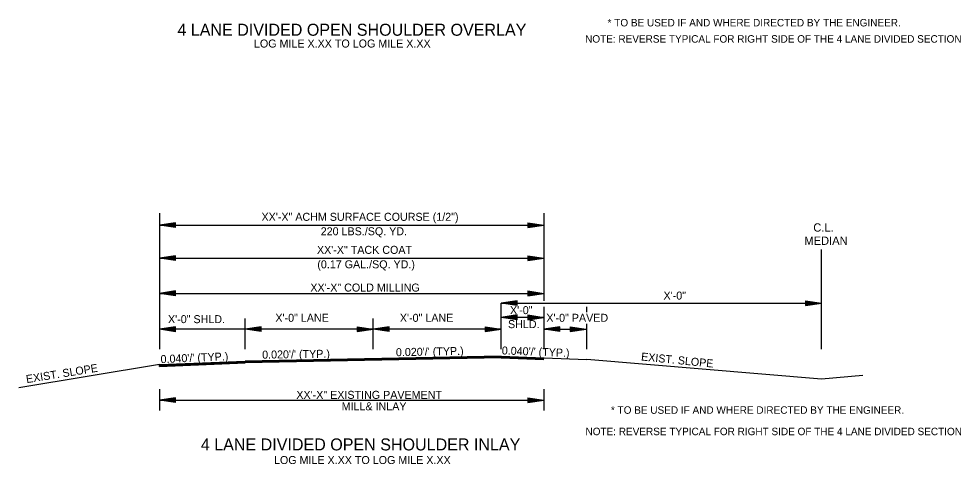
# Model space of a CAD drawing. Extents: x 542112 to 1930787, y -1968972 to 596640.
# Drawn here: x 546552 to 547435, y -1965039 to -1964622 of the extents above; entities that cross this region are included whole.
import ezdxf

# ---------------------------------------------------------------- set-up
doc = ezdxf.new("R2010")
doc.units = 0
doc.layers.add('R_Border Prem', color=7, linetype='Continuous')
doc.layers.add('R_Draft', color=7, linetype='Continuous')

msp = doc.modelspace()

# ---------------------------------------------------------------- linework, layer by layer
at = {"layer": 'R_Draft'}
for p, q in [((546683.85, -1964804.05), (546683.85, -1964931.48)), ((546698.85, -1964813.06), (546683.85, -1964815.31)), ((546683.85, -1964815.31), (547044.01, -1964815.31)), ((546698.85, -1964817.56), (546683.85, -1964815.31)), ((546698.85, -1964813.44), (546686.35, -1964815.31)), ((546698.85, -1964817.19), (546686.35, -1964815.31)), ((546698.85, -1964813.82), (546688.93, -1964815.31)), ((546698.85, -1964816.81), (546688.93, -1964815.31)), ((546698.85, -1964814.2), (546691.43, -1964815.31)), ((546698.85, -1964816.43), (546691.43, -1964815.31)), ((546698.85, -1964814.58), (546693.97, -1964815.31)), ((546698.85, -1964816.04), (546693.97, -1964815.31)), ((546698.85, -1964814.96), (546696.48, -1964815.31)), ((546698.85, -1964815.67), (546696.48, -1964815.31)), ((546698.85, -1964817.56), (546698.85, -1964813.06)), ((547029.01, -1964813.06), (547044.01, -1964815.31)), ((547029.01, -1964813.06), (547029.01, -1964817.56)), ((547029.01, -1964813.44), (547041.51, -1964815.31)), ((547029.01, -1964813.82), (547038.93, -1964815.31)), ((547029.01, -1964814.2), (547036.43, -1964815.31)), ((547029.01, -1964814.59), (547033.89, -1964815.31)), ((547029.01, -1964814.96), (547031.38, -1964815.31)), ((547029.01, -1964817.56), (547044.01, -1964815.31)), ((547029.01, -1964816.05), (547033.89, -1964815.31)), ((547029.01, -1964816.81), (547038.93, -1964815.31)), ((547029.01, -1964817.19), (547041.51, -1964815.31)), ((547029.01, -1964816.43), (547036.43, -1964815.31)), ((547029.01, -1964815.67), (547031.38, -1964815.31)), ((547304.03, -1964931.31), (547304.03, -1964837.92)), ((546698.85, -1964843.93), (546683.85, -1964846.18)), ((546683.85, -1964846.18), (547044.01, -1964846.18)), ((546698.85, -1964848.43), (546683.85, -1964846.18)), ((546698.85, -1964844.31), (546686.35, -1964846.18)), ((546698.85, -1964848.06), (546686.35, -1964846.18)), ((546698.85, -1964844.69), (546688.93, -1964846.18)), ((546698.85, -1964847.68), (546688.93, -1964846.18)), ((546698.85, -1964845.07), (546691.43, -1964846.18)), ((546698.85, -1964847.3), (546691.43, -1964846.18)), ((546698.85, -1964845.45), (546693.97, -1964846.18)), ((546698.85, -1964846.91), (546693.97, -1964846.18)), ((546698.85, -1964845.83), (546696.48, -1964846.18)), ((546698.85, -1964846.54), (546696.48, -1964846.18)), ((546698.85, -1964848.43), (546698.85, -1964843.93)), ((547029.01, -1964843.93), (547044.01, -1964846.18)), ((547029.01, -1964843.93), (547029.01, -1964848.43)), ((547029.01, -1964844.31), (547041.51, -1964846.18)), ((547029.01, -1964844.69), (547038.93, -1964846.18)), ((547029.01, -1964845.07), (547036.43, -1964846.18)), ((547029.01, -1964845.46), (547033.89, -1964846.18)), ((547029.01, -1964845.83), (547031.38, -1964846.18)), ((547029.01, -1964848.43), (547044.01, -1964846.18)), ((547029.01, -1964846.92), (547033.89, -1964846.18)), ((547029.01, -1964847.68), (547038.93, -1964846.18)), ((547029.01, -1964848.06), (547041.51, -1964846.18)), ((547029.01, -1964847.3), (547036.43, -1964846.18)), ((547029.01, -1964846.54), (547031.38, -1964846.18)), ((546698.85, -1964876.86), (546683.85, -1964879.11)), ((546698.85, -1964877.24), (546686.35, -1964879.11)), ((546698.85, -1964877.62), (546688.93, -1964879.11)), ((546698.85, -1964877.99), (546691.43, -1964879.11)), ((546698.85, -1964878.38), (546693.97, -1964879.11)), ((546698.85, -1964878.76), (546696.48, -1964879.11)), ((546698.85, -1964881.36), (546698.85, -1964876.86)), ((547029.01, -1964876.86), (547044.01, -1964879.11)), ((547029.01, -1964876.86), (547029.01, -1964881.36)), ((547029.01, -1964877.24), (547041.51, -1964879.11)), ((547029.01, -1964877.62), (547038.93, -1964879.11)), ((547029.01, -1964877.99), (547036.43, -1964879.11)), ((547029.01, -1964878.38), (547033.89, -1964879.11)), ((547029.01, -1964878.76), (547031.38, -1964879.11)), ((546683.85, -1964879.11), (547044.01, -1964879.11)), ((546698.85, -1964881.36), (546683.85, -1964879.11)), ((546698.85, -1964880.99), (546686.35, -1964879.11)), ((546698.85, -1964880.6), (546688.93, -1964879.11)), ((546698.85, -1964880.23), (546691.43, -1964879.11)), ((546698.85, -1964879.84), (546693.97, -1964879.11)), ((546698.85, -1964879.46), (546696.48, -1964879.11)), ((547019.03, -1964886.13), (547004.03, -1964888.38)), ((547019.03, -1964886.5), (547006.54, -1964888.38)), ((547019.03, -1964886.88), (547009.12, -1964888.38)), ((547019.03, -1964887.26), (547011.62, -1964888.38)), ((547019.03, -1964890.63), (547019.03, -1964886.13)), ((547029.01, -1964881.36), (547044.01, -1964879.11)), ((547029.01, -1964879.85), (547033.89, -1964879.11)), ((547029.01, -1964880.6), (547038.93, -1964879.11)), ((547029.01, -1964880.99), (547041.51, -1964879.11)), ((547029.01, -1964880.23), (547036.43, -1964879.11)), ((547029.01, -1964879.46), (547031.38, -1964879.11)), ((547289.03, -1964886.13), (547304.03, -1964888.38)), ((547289.03, -1964886.13), (547289.03, -1964890.63)), ((547289.03, -1964886.5), (547301.53, -1964888.38)), ((547289.03, -1964886.88), (547298.95, -1964888.38)), ((547289.03, -1964887.26), (547296.45, -1964888.38)), ((547004.03, -1964931.31), (547004.03, -1964888.38)), ((547004.03, -1964888.38), (547304.03, -1964888.38)), ((547019.03, -1964890.63), (547004.03, -1964888.38)), ((547019.03, -1964890.25), (547006.54, -1964888.38)), ((547019.03, -1964889.87), (547009.12, -1964888.38)), ((547019.03, -1964889.49), (547011.62, -1964888.38)), ((547019.03, -1964887.64), (547014.16, -1964888.38)), ((547019.03, -1964889.1), (547014.16, -1964888.38)), ((547019.03, -1964888.02), (547016.66, -1964888.38)), ((547019.03, -1964888.73), (547016.66, -1964888.38)), ((547084.29, -1964896.77), (547084.29, -1964891.87)), ((547289.03, -1964887.65), (547293.91, -1964888.38)), ((547289.03, -1964888.02), (547291.4, -1964888.38)), ((547289.03, -1964890.63), (547304.03, -1964888.38)), ((547289.03, -1964889.11), (547293.91, -1964888.38)), ((547289.03, -1964889.87), (547298.95, -1964888.38)), ((547289.03, -1964890.25), (547301.53, -1964888.38)), ((547289.03, -1964889.49), (547296.45, -1964888.38)), ((547289.03, -1964888.73), (547291.4, -1964888.38)), ((546764.11, -1964931.31), (546764.11, -1964902.76)), ((546764.11, -1964931.48), (546764.11, -1964902.76)), ((546884.11, -1964931.31), (546884.11, -1964902.76)), ((547019.03, -1964899.36), (547004.03, -1964901.61)), ((547044.01, -1964901.61), (547004.03, -1964901.61)), ((547019.03, -1964903.86), (547004.03, -1964901.61)), ((547004.03, -1964912.65), (547004.03, -1964902.76)), ((547019.03, -1964899.74), (547006.54, -1964901.61)), ((547019.03, -1964903.49), (547006.54, -1964901.61)), ((547019.03, -1964900.12), (547009.12, -1964901.61)), ((547019.03, -1964903.11), (547009.12, -1964901.61)), ((547019.03, -1964900.5), (547011.62, -1964901.61)), ((547019.03, -1964902.73), (547011.62, -1964901.61)), ((547019.03, -1964900.88), (547014.16, -1964901.61)), ((547019.03, -1964902.34), (547014.16, -1964901.61)), ((547019.03, -1964901.26), (547016.66, -1964901.61)), ((547019.03, -1964901.97), (547016.66, -1964901.61)), ((547019.03, -1964903.86), (547019.03, -1964899.36)), ((547029.01, -1964899.36), (547044.01, -1964901.61)), ((547029.01, -1964899.36), (547029.01, -1964903.86)), ((547029.01, -1964899.74), (547041.51, -1964901.61)), ((547029.01, -1964900.12), (547038.93, -1964901.61)), ((547029.01, -1964900.5), (547036.43, -1964901.61)), ((547029.01, -1964900.89), (547033.89, -1964901.61)), ((547029.01, -1964901.26), (547031.38, -1964901.61)), ((547029.01, -1964903.86), (547044.01, -1964901.61)), ((547029.01, -1964902.35), (547033.89, -1964901.61)), ((547029.01, -1964903.11), (547038.93, -1964901.61)), ((547029.01, -1964903.49), (547041.51, -1964901.61)), ((547029.01, -1964902.73), (547036.43, -1964901.61)), ((547029.01, -1964901.97), (547031.38, -1964901.61)), ((546698.85, -1964910.57), (546683.85, -1964912.82)), ((546764.11, -1964912.82), (546683.85, -1964912.82)), ((546698.85, -1964915.07), (546683.85, -1964912.82)), ((546698.85, -1964910.94), (546686.35, -1964912.82)), ((546698.85, -1964914.69), (546686.35, -1964912.82)), ((546698.85, -1964911.33), (546688.93, -1964912.82)), ((546698.85, -1964914.31), (546688.93, -1964912.82)), ((546698.85, -1964911.7), (546691.43, -1964912.82)), ((546698.85, -1964913.94), (546691.43, -1964912.82)), ((546698.85, -1964912.08), (546693.97, -1964912.82)), ((546698.85, -1964913.55), (546693.97, -1964912.82)), ((546698.85, -1964912.47), (546696.48, -1964912.82)), ((546698.85, -1964913.17), (546696.48, -1964912.82)), ((546698.85, -1964915.07), (546698.85, -1964910.57)), ((546779.11, -1964910.4), (546764.11, -1964912.65)), ((546884.11, -1964912.65), (546764.11, -1964912.65)), ((546779.11, -1964914.9), (546764.11, -1964912.65)), ((546779.11, -1964910.77), (546766.61, -1964912.65)), ((546779.11, -1964914.52), (546766.61, -1964912.65)), ((546779.11, -1964911.16), (546769.19, -1964912.65)), ((546779.11, -1964914.14), (546769.19, -1964912.65)), ((546779.11, -1964911.53), (546771.69, -1964912.65)), ((546779.11, -1964913.77), (546771.69, -1964912.65)), ((546779.11, -1964911.91), (546774.23, -1964912.65)), ((546779.11, -1964913.38), (546774.23, -1964912.65)), ((546779.11, -1964912.3), (546776.74, -1964912.65)), ((546779.11, -1964913), (546776.74, -1964912.65)), ((546779.11, -1964914.9), (546779.11, -1964910.4)), ((546869.11, -1964910.4), (546884.11, -1964912.65)), ((546869.11, -1964910.4), (546869.11, -1964914.9)), ((546869.11, -1964910.77), (546881.6, -1964912.65)), ((546869.11, -1964911.16), (546879.02, -1964912.65)), ((546869.11, -1964911.53), (546876.52, -1964912.65)), ((546869.11, -1964911.92), (546873.98, -1964912.65)), ((546869.11, -1964912.3), (546871.48, -1964912.65)), ((546869.11, -1964914.9), (546884.11, -1964912.65)), ((546869.11, -1964913.38), (546873.98, -1964912.65)), ((546869.11, -1964914.14), (546879.02, -1964912.65)), ((546869.11, -1964914.52), (546881.6, -1964912.65)), ((546869.11, -1964913.77), (546876.52, -1964912.65)), ((546869.11, -1964913), (546871.48, -1964912.65)), ((546899.11, -1964910.4), (546884.11, -1964912.65)), ((547004.03, -1964912.65), (546884.11, -1964912.65)), ((546899.11, -1964914.9), (546884.11, -1964912.65)), ((546899.11, -1964910.77), (546886.61, -1964912.65)), ((546899.11, -1964914.52), (546886.61, -1964912.65)), ((546899.11, -1964911.16), (546889.19, -1964912.65)), ((546899.11, -1964914.14), (546889.19, -1964912.65)), ((546899.11, -1964911.53), (546891.69, -1964912.65)), ((546899.11, -1964913.77), (546891.69, -1964912.65)), ((546899.11, -1964911.91), (546894.23, -1964912.65)), ((546899.11, -1964913.38), (546894.23, -1964912.65)), ((546899.11, -1964912.3), (546896.74, -1964912.65)), ((546899.11, -1964913), (546896.74, -1964912.65)), ((546899.11, -1964914.9), (546899.11, -1964910.4)), ((546989.03, -1964910.4), (547004.03, -1964912.65)), ((546989.03, -1964910.4), (546989.03, -1964914.9)), ((546989.03, -1964910.77), (547001.53, -1964912.65)), ((546989.03, -1964911.16), (546998.95, -1964912.65)), ((546989.03, -1964911.53), (546996.45, -1964912.65)), ((546989.03, -1964911.92), (546993.91, -1964912.65)), ((546989.03, -1964912.3), (546991.4, -1964912.65)), ((546989.03, -1964914.9), (547004.03, -1964912.65)), ((546989.03, -1964913.38), (546993.91, -1964912.65)), ((546989.03, -1964914.14), (546998.95, -1964912.65)), ((546989.03, -1964914.52), (547001.53, -1964912.65)), ((546989.03, -1964913.77), (546996.45, -1964912.65)), ((546989.03, -1964913), (546991.4, -1964912.65)), ((547004.03, -1964931.31), (547004.03, -1964912.65)), ((547059.01, -1964910.4), (547044.01, -1964912.65)), ((547059.01, -1964914.9), (547044.01, -1964912.65)), ((547044.01, -1964912.65), (547083.56, -1964912.65)), ((547059.01, -1964910.77), (547046.52, -1964912.65)), ((547059.01, -1964914.52), (547046.52, -1964912.65)), ((547059.01, -1964911.16), (547049.1, -1964912.65)), ((547059.01, -1964914.14), (547049.1, -1964912.65)), ((547059.01, -1964911.53), (547051.59, -1964912.65)), ((547059.01, -1964913.77), (547051.59, -1964912.65)), ((547059.01, -1964911.91), (547054.14, -1964912.65)), ((547059.01, -1964913.38), (547054.14, -1964912.65)), ((547059.01, -1964912.3), (547056.64, -1964912.65)), ((547059.01, -1964913), (547056.64, -1964912.65)), ((547059.01, -1964914.9), (547059.01, -1964910.4)), ((547068.56, -1964910.4), (547083.56, -1964912.65)), ((547068.56, -1964910.4), (547068.56, -1964914.9)), ((547068.56, -1964910.77), (547081.05, -1964912.65)), ((547068.56, -1964911.16), (547078.47, -1964912.65)), ((547068.56, -1964911.53), (547075.97, -1964912.65)), ((547068.56, -1964911.92), (547073.43, -1964912.65)), ((547068.56, -1964912.3), (547070.93, -1964912.65)), ((547068.56, -1964914.9), (547083.56, -1964912.65)), ((547068.56, -1964913.38), (547073.43, -1964912.65)), ((547068.56, -1964914.14), (547078.47, -1964912.65)), ((547068.56, -1964914.52), (547081.05, -1964912.65)), ((547068.56, -1964913.77), (547075.97, -1964912.65)), ((547068.56, -1964913), (547070.93, -1964912.65)), ((547084.29, -1964931.31), (547084.29, -1964907.62)), ((547004.03, -1964937.86), (546764.11, -1964942.65)), ((547004.03, -1964938.16), (546764.11, -1964942.95)), ((547004.03, -1964938.46), (546764.12, -1964943.25)), ((547004.03, -1964938.76), (546764.12, -1964943.55)), ((547004.03, -1964939.06), (546764.13, -1964943.85)), ((547004.03, -1964939.36), (546764.14, -1964944.15)), ((547004.03, -1964939.56), (546764.14, -1964944.35)), ((547003.97, -1964939.36), (547044.01, -1964940.96)), ((547003.97, -1964939.56), (547044.01, -1964941.16)), ((547003.99, -1964939.06), (547044.01, -1964940.66)), ((547004, -1964938.76), (547044.01, -1964940.36)), ((547004.01, -1964938.46), (547044.01, -1964940.06)), ((547004.02, -1964938.16), (547044.01, -1964939.76)), ((547004.03, -1964937.86), (547044.31, -1964939.47)), ((547044.01, -1964939.46), (547084.29, -1964941.07)), ((546683.85, -1964945.87), (546552.17, -1964967.81)), ((546683.85, -1964945.87), (546764.11, -1964942.65)), ((546683.85, -1964946.17), (546764.12, -1964942.95)), ((546683.85, -1964946.47), (546764.13, -1964943.25)), ((546683.85, -1964946.77), (546764.14, -1964943.55)), ((546683.85, -1964947.07), (546764.15, -1964943.85)), ((546683.85, -1964947.37), (546764.17, -1964944.15)), ((546683.85, -1964947.57), (546764.17, -1964944.35)), ((546683.85, -1964947.57), (546683.85, -1964945.87)), ((546683.85, -1964947.57), (546683.85, -1964945.87)), ((547303.96, -1964959.48), (547084.29, -1964941.07)), ((547342.79, -1964956.22), (547303.96, -1964959.48)), ((546683.85, -1964969.05), (546683.85, -1964989.05)), ((547044.01, -1964969.05), (547044.01, -1964989.05)), ((546698.85, -1964977.05), (546683.85, -1964979.3)), ((546683.85, -1964979.3), (547044.01, -1964979.3)), ((546698.85, -1964981.55), (546683.85, -1964979.3)), ((546698.85, -1964977.43), (546686.35, -1964979.3)), ((546698.85, -1964981.18), (546686.35, -1964979.3)), ((546698.85, -1964977.81), (546688.93, -1964979.3)), ((546698.85, -1964980.8), (546688.93, -1964979.3)), ((546698.85, -1964978.19), (546691.43, -1964979.3)), ((546698.85, -1964980.42), (546691.43, -1964979.3)), ((546698.85, -1964978.57), (546693.97, -1964979.3)), ((546698.85, -1964980.03), (546693.97, -1964979.3)), ((546698.85, -1964978.95), (546696.48, -1964979.3)), ((546698.85, -1964979.66), (546696.48, -1964979.3)), ((546698.85, -1964981.55), (546698.85, -1964977.05)), ((547029.01, -1964977.05), (547044.01, -1964979.3)), ((547029.01, -1964977.05), (547029.01, -1964981.55)), ((547029.01, -1964977.43), (547041.51, -1964979.3)), ((547029.01, -1964977.81), (547038.93, -1964979.3)), ((547029.01, -1964978.19), (547036.43, -1964979.3)), ((547029.01, -1964978.58), (547033.89, -1964979.3)), ((547029.01, -1964978.95), (547031.38, -1964979.3)), ((547029.01, -1964981.55), (547044.01, -1964979.3)), ((547029.01, -1964980.04), (547033.89, -1964979.3)), ((547029.01, -1964980.8), (547038.93, -1964979.3)), ((547029.01, -1964981.18), (547041.51, -1964979.3)), ((547029.01, -1964980.42), (547036.43, -1964979.3)), ((547029.01, -1964979.66), (547031.38, -1964979.3))]:
    msp.add_line(p, q, dxfattribs=at)
for points in [[(547044.01, -1964804.05), (547044.01, -1964886.15)], [(547044.01, -1964891.87), (547044.01, -1964931.31)]]:
    msp.add_lwpolyline(points, dxfattribs=at)

# ---------------------------------------------------------------- texts
at = {"layer": 'R_Border Prem'}
for s, p in [('* TO BE USED IF AND WHERE DIRECTED BY THE ENGINEER.', (547103.62, -1964628.97)), ('NOTE: REVERSE TYPICAL FOR RIGHT SIDE OF THE 4 LANE DIVIDED SECTION', (547082.56, -1964644.18)), ('* TO BE USED IF AND WHERE DIRECTED BY THE ENGINEER.', (547106.74, -1964991.97)), ('NOTE: REVERSE TYPICAL FOR RIGHT SIDE OF THE 4 LANE DIVIDED SECTION', (547082.92, -1965012.04))]:
    msp.add_text(s, height=7, dxfattribs=at).set_placement(p)
at = {"layer": 'R_Draft'}
for s, height, p in [('4 LANE DIVIDED OPEN SHOULDER OVERLAY', 11.25, (546700.7, -1964637.72)), ('LOG MILE X.XX TO LOG MILE X.XX', 7.5, (546772.38, -1964648.76)), ('XX\'-X" ACHM SURFACE COURSE (1/2")', 7.5, (546779.45, -1964811.15)), ('220 LBS./SQ. YD. ', 7.5, (546834.93, -1964824.69)), ('C.L.', 7.8, (547296.34, -1964821.31)), ('XX\'-X" TACK COAT', 7.5, (546831.39, -1964842.11)), ('MEDIAN', 7.8, (547287.92, -1964833.68)), ('(0.17 GAL./SQ. YD.)', 7.5, (546831.74, -1964855.65)), ('XX\'-X" COLD MILLING', 7.5, (546825.22, -1964877.45)), ('X\'-0" ', 7.5, (547156.01, -1964884.96)), ('X\'-0" ', 7.5, (547012.22, -1964898.59)), ('X\'-0" SHLD.', 7.5, (546691.88, -1964907.05)), ('X\'-0" LANE', 7.5, (546792.45, -1964905.79)), ('X\'-0" LANE', 7.5, (546909.04, -1964905.79)), ('SHLD.', 7.5, (547010.33, -1964911.72)), ('X\'-0" PAVED', 7.5, (547046.26, -1964905.79)), ('XX\'-X" EXISTING PAVEMENT', 7.5, (546812.09, -1964977.98)), ('MILL& INLAY', 7.5, (546854.52, -1964988.7)), ('4 LANE DIVIDED OPEN SHOULDER INLAY', 11.25, (546722.63, -1965026.33)), ('LOG MILE X.XX TO LOG MILE X.XX', 7.5, (546791.15, -1965039.08))]:
    msp.add_text(s, height=height, dxfattribs=at).set_placement(p)
for s, rotation, p in [("0.020'/' (TYP.)", 0.87191, (546780.12, -1964940.35)), ("0.020'/' (TYP.)", 1.17446, (546905.42, -1964938.06)), ("0.040'/' (TYP.)", 357.81683, (547004.42, -1964936.33)), ("0.040'/' (TYP.)", 2.44797, (546685.08, -1964944.55)), ('EXIST. SLOPE', 354.30267, (547134.73, -1964941.96)), ('EXIST. SLOPE', 9.15344, (546559.52, -1964963.29))]:
    msp.add_text(s, height=7.5, rotation=rotation, dxfattribs=at).set_placement(p)

doc.saveas('drawing.dxf')
